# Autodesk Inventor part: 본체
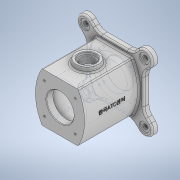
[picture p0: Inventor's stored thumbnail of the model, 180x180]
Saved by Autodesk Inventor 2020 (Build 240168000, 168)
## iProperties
Created: 2022-01
Part Number: 본체
Material: 일반
Document SubType Name: Modeling
Designer: user
Density: 1 g/cm^3
Appearance: 기본값
Author: user
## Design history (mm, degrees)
sketch "스케치1"
  geometry: L1 (-53, -53)-(53, -53); L2 (53, -53)-(53, 53); L3 (53, 53)-(-53, 53); L4 (-53, 53)-(-53, -53); L5 (-53, -53)-(53, 53); L6 (53, -53)-(-53, 53); L7 (-54.447, -54.447)-(54.447, 54.447); L8 (-43.841, -65.054)-(65.054, 43.841); L9 (43.841, 65.054)-(-65.054, -43.841); L10 (-54.447, 54.447)-(54.447, -54.447); L11 (-65.054, 43.841)-(43.841, -65.054); L12 (65.054, -43.841)-(-43.841, 65.054); A1 r 15 centre (-54.447, -54.447) between (-65.054, -43.841) and (-43.841, -65.054); A2 r 15 centre (54.447, 54.447) between (65.054, 43.841) and (43.841, 65.054); A3 r 15 centre (-54.447, 54.447) between (-43.841, 65.054) and (-65.054, 43.841); A4 r 15 centre (54.447, -54.447) between (43.841, -65.054) and (65.054, -43.841); 9 further points
  constraints: 28 end point, 8 point on circle, 8 tangent, 4 centre point, 4 midpoint, 4 parallel, 2 point on line, 1 horizontal, 1 perpendicular
  dimensions: "d21" = 106 distance of L3.end L2.end; "d22" = 106 distance of L2.end L1.end; "d23" = 30 diameter of A2; "d24" = 30 distance between parallel lines of L11 L12; "d25" = 154 distance of L10.end L10.start; "d26" = 154 distance of L7.end L7.start
node "작업 평면1"
sketch "스케치2"
  geometry: L1 (-32.942, -45)-(0, -45); L2 (0, 45)-(-32.942, 45); L3 (0, 45)-(32.942, 45); L4 (32.942, -45)-(0, -45); A1 r 90 centre (45, 0) between (-32.942, 45) and (-32.942, -45); A2 r 90 centre (-45, 0) between (32.942, -45) and (32.942, 45)
  constraints: 8 end point, 4 point on circle, 2 centre point, 1 horizontal, 1 parallel
extrude "돌출2" join sketch "스케치2" distance "d13" = 100; taper "d14" = 0 deg
extrude "돌출3" join sketch "스케치1" distance "d27" = 10; taper "d28" = 0 deg
fillet "모깎기2" dims "d29" = 20
sketch "스케치4"
  geometry: L1 (45, 110)-(-45, 110) reference; L2 (0, 110)-(0, 0); L3 (0, 110)-(25, 110); L4 (25, 110)-(25, 98); L5 (25, 98)-(37, 98); L6 (37, 98)-(37, 12); L7 (37, 12)-(25, 12); L8 (25, 12)-(25, 0); L9 (23.503, 0)-(37.645, 0) reference; L10 (25, 0)-(0, 0); L11 (23.503, 0)-(23.503, 10) reference; 1 further point
  constraints: 16 end point, 4 perpendicular, 2 point on line, 1 horizontal, 1 midpoint, 1 parallel, 1 vertical
  dimensions: "d30" = 25 distance of L2.start L3.end; "d31" = 12 distance of L3.end L4.end; "d32" = 12 distance of L4.end L5.end; "d33" = 86 distance of L5.end L6.end
revolve "회전2" sketch "스케치4" stored, may be unused: angle "d34" = 90 deg
node "작업 평면2"
sketch "스케치5"
  geometry: L1 (0, 0)-(0, 60); C1 r 20 at (0, 60)
  constraints: 2 end point, 1 centre point, 1 coincident, 1 vertical
  dimensions: "d36" = 60 distance of L1.start L1.end; "d37" = 40 diameter of C1
extrude "돌출4" join sketch "스케치5" stored distance "d38" = 10; taper "d39" = 15 deg
sketch "스케치6"
  geometry: C1 r 20 at (0, 0) reference; 2 further points
  constraints: 1 coincident
hole "구멍1" sketch "스케치6" at (0, 0) diameter "d40" = 24; stored, may be unused: countersink angle "d44" = 90 deg, drill point angle "d46" = 0 deg; dims "d41" = 8, "d42" = 30, "d43" = 5, "d45" = 39.5
chamfer "모따기1" distance "d47" = 1; stored, may be unused: second distance "d48" = 2, angle "d49" = 45 deg
chamfer "모따기3" distance "d53" = 1; stored, may be unused: second distance "d54" = 2, angle "d55" = 45 deg
sketch "스케치7"
  geometry: 1 further point
sketch "스케치8"
  geometry: A1 r 15 centre (-54.447, 54.447) between (-43.841, 65.054) and (-65.054, 43.841) reference; A2 r 15 centre (54.447, 54.447) between (65.054, 43.841) and (43.841, 65.054) reference; A3 r 15 centre (54.447, -54.447) between (43.841, -65.054) and (65.054, -43.841) reference; A4 r 15 centre (-54.447, -54.447) between (-65.054, -43.841) and (-43.841, -65.054) reference; 5 further points
  constraints: 4 coincident
hole "구멍2" sketch "스케치8" at (-54.447, 54.447), (54.447, 54.447), (54.447, -54.447), (-54.447, -54.447) diameter "d56" = 9; stored, may be unused: countersink angle "d60" = 90 deg, drill point angle "d62" = 0 deg; dims "d57" = 8, "d58" = 18, "d59" = 2, "d61" = 39.5
sketch "스케치9"
  geometry: L1 (0, 0)-(-46.362, 46.362); L2 (0, 0)-(65.566, 0); L3 (0, 0)-(0, 40); A1 r 40 centre (0, 0) between (0, 40) and (-28.284, 28.284); 1 further point
  constraints: 6 end point, 2 point on circle, 1 centre point, 1 coincident, 1 equal length, 1 horizontal, 1 point on line, 1 vertical
  dimensions: "d63" = 80 diameter of A1; "d65" = 45 deg angle of L1 L3
hole "구멍3" sketch "스케치9" at (-28.284, 28.284) diameter "d66" = 3.242; stored, may be unused: countersink angle "d70" = 90 deg, drill point angle "d72" = 118 deg; dims "d67" = 8, "d68" = 18, "d69" = 2, "d71" = 10
sketch "스케치10"
  geometry: L1 (0, 0)-(-44.978, 44.978); L2 (0, 0)-(63.609, 0); C1 r 25 at (0, 0) reference; C2 r 40 at (0, 0); C3 r 1.621 at (-28.284, 28.284) reference; 2 further points
  constraints: 4 end point, 2 coincident, 1 centre point, 1 equal length, 1 horizontal
  dimensions: "d76" = 80 diameter of C2; "d77" = 135 deg angle of L2 L1
hole "구멍4" sketch "스케치10" at (-28.284, 28.284) diameter "d78" = 3.242; stored, may be unused: countersink angle "d82" = 90 deg, drill point angle "d84" = 118 deg; dims "d79" = 8, "d80" = 18, "d81" = 2, "d83" = 10
fillet "모깎기3" dims "d88" = 3
fillet "모깎기4" dims "d89" = 3
fillet "모깎기5" dims "d90" = 3
chamfer "모따기4" distance "d91" = 1; stored, may be unused: second distance "d92" = 2, angle "d93" = 45 deg
chamfer "모따기5" distance "d94" = 1; stored, may be unused: second distance "d95" = 2, angle "d96" = 45 deg
node "작업 평면3"
sketch "스케치11"
  geometry: L1 (53, 40)-(53, 80) reference; L2 (69.447, 0)-(43.841, 0) reference; 3 further points
  constraints: 1 other
feature "엠보싱1" sketch "스케치11" dims "d21" = 106, "d22" = 106, "d23" = 30, "d24" = 30, "d25" = 154, "d26" = 154, "d98" = 0.5, "d99" = 0
node "솔리드1"
pattern_circular "원형 패턴1" dims angle "d74" = 360 deg
pattern_circular "원형 패턴2" dims angle "d86" = 360 deg
feature "A9D066F2-1C7D-4E18-AEED-F7BC21143FA4" dims "d40" = 24, "d41" = 8, "d42" = 30, "d43" = 5, "d44" = 90 deg, "d45" = 39.5, "d46" = 0
other parameters: "d35" = 53, "d97" = 45
